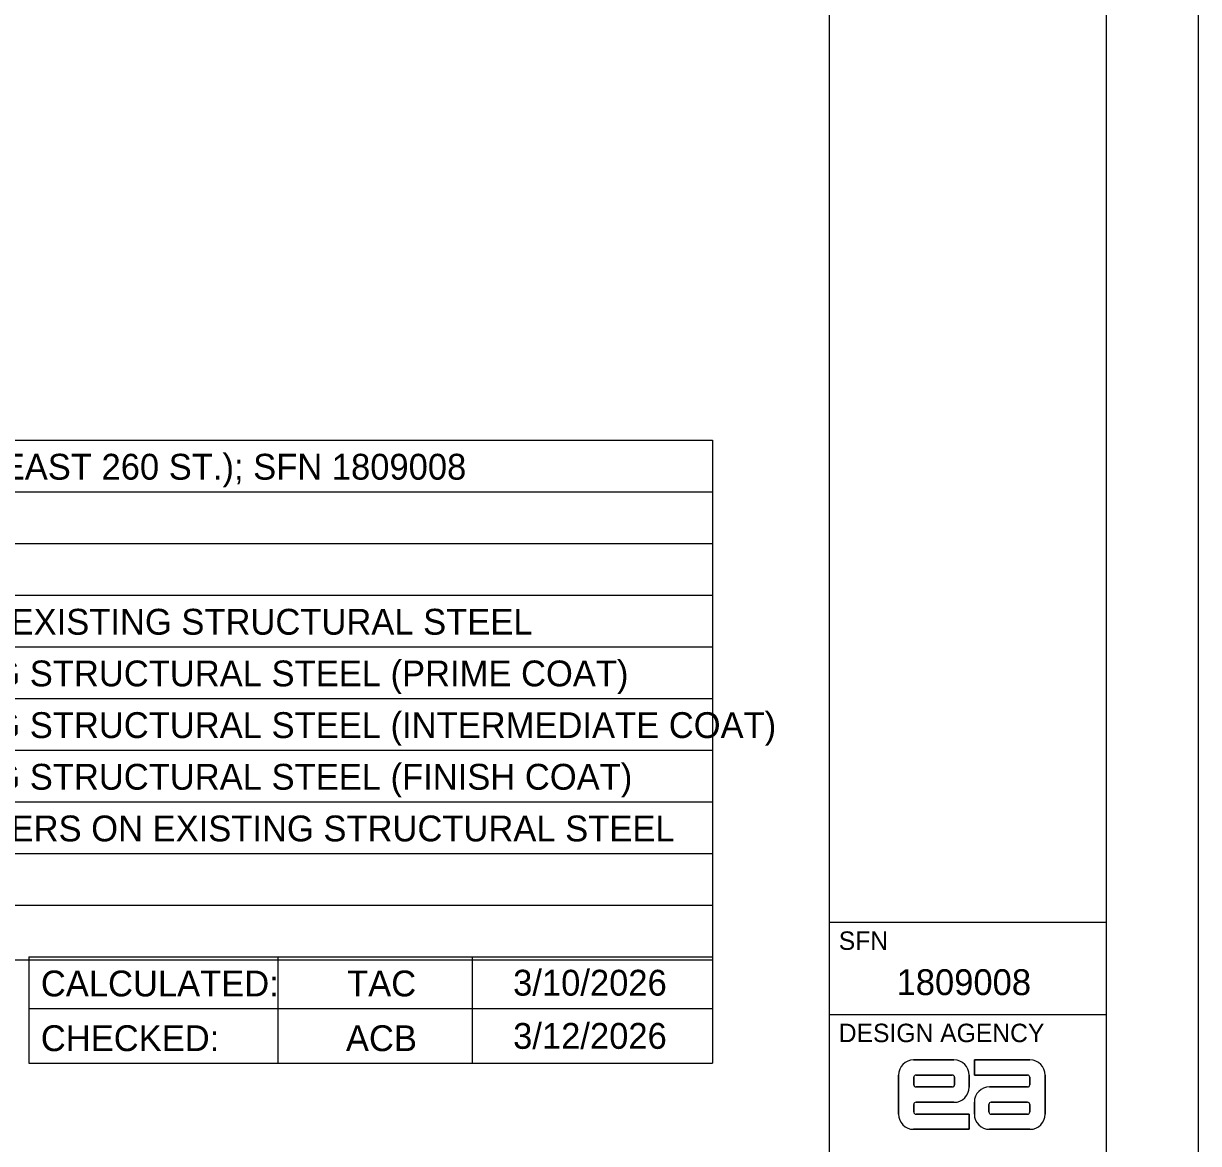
# Model space of a CAD drawing. Extents: x 0 to 34, y 0 to 22.
# Drawn here: x 27.63 to 34, y 4.3 to 10.37 of the extents above; entities that cross this region are included whole.
import ezdxf

# ---------------------------------------------------------------- set-up
doc = ezdxf.new("R2010")
doc.units = 0
for name, color, linetype in [('SH_Border', 7, 'Continuous'), ('SH_Cut_Line', 7, 'Continuous'), ('SH_Data', 7, 'Continuous'), ('SH_Text', 7, 'Continuous'), ('TX_X_20', 7, 'Continuous')]:
    doc.layers.add(name, color=color, linetype=linetype)

msp = doc.modelspace()

# ---------------------------------------------------------------- linework, layer by layer
at = {"layer": 'SH_Border'}
for p, q in [((32, 0.5), (32, 21.5)), ((32, 5.5), (33.5, 5.5)), ((32, 5), (33.5, 5))]:
    msp.add_line(p, q, dxfattribs=at)
msp.add_lwpolyline([(1.5, 21.5), (33.5, 21.5), (33.5, 0.5), (1.5, 0.5)], close=True, dxfattribs=at)
at = {"layer": 'SH_Cut_Line'}
msp.add_lwpolyline([(0, 0), (34, 0), (34, 22), (0, 22)], close=True, dxfattribs=at)
at = {"layer": 'SH_Text'}
for p, q in [((21.4824, 8.1121), (31.3648, 8.1121)), ((31.3648, 8.1121), (31.3648, 5.2956)), ((21.4824, 7.8321), (31.3648, 7.8321)), ((21.4824, 7.5521), (31.3648, 7.5521)), ((21.4824, 7.272), (31.3648, 7.272)), ((21.4824, 6.992), (31.3648, 6.992)), ((21.4824, 6.712), (31.3648, 6.712)), ((21.4824, 6.432), (31.3648, 6.432)), ((21.4824, 6.152), (31.3648, 6.152)), ((21.4824, 5.872), (31.3648, 5.872)), ((21.4824, 5.592), (31.3648, 5.592)), ((21.4824, 5.2956), (31.3648, 5.2956)), ((27.6589, 5.312), (31.3648, 5.312)), ((27.6589, 5.312), (27.6589, 4.7356)), ((29.0095, 5.312), (29.0095, 4.7356)), ((30.0636, 5.312), (30.0636, 4.7356)), ((31.3648, 5.312), (31.3648, 4.7356)), ((27.6589, 5.032), (31.3648, 5.032)), ((27.6589, 4.7356), (31.3648, 4.7356))]:
    msp.add_line(p, q, dxfattribs=at)
at = {"layer": 'TX_X_20'}
for p, q in [((32.6745, 4.7533), (32.456, 4.7533)), ((32.456, 4.7533), (32.6745, 4.7533)), ((32.785, 4.7533), (33.0865, 4.7533)), ((32.785, 4.6713), (32.785, 4.7533)), ((32.3739, 4.6713), (32.3739, 4.4597)), ((32.3739, 4.4597), (32.3739, 4.6713)), ((32.457, 4.6189), (32.457, 4.6594)), ((32.457, 4.6594), (32.457, 4.6189)), ((32.4688, 4.6713), (32.6656, 4.6713)), ((32.6656, 4.6713), (32.4688, 4.6713)), ((32.6775, 4.6594), (32.6775, 4.6189)), ((32.6775, 4.6189), (32.6775, 4.6594)), ((32.7566, 4.606), (32.7566, 4.6713)), ((32.7566, 4.6713), (32.7566, 4.606)), ((33.0737, 4.6713), (32.785, 4.6713)), ((33.0855, 4.6594), (33.0855, 4.6189)), ((33.0855, 4.6189), (33.0855, 4.6594)), ((33.1686, 4.4597), (33.1686, 4.6713)), ((33.1686, 4.6713), (33.1686, 4.4597)), ((32.6656, 4.607), (32.4688, 4.607)), ((32.4688, 4.607), (32.6656, 4.607)), ((33.0737, 4.607), (32.8671, 4.607)), ((32.8671, 4.607), (33.0737, 4.607)), ((32.4688, 4.524), (32.6745, 4.524)), ((32.6745, 4.524), (32.4688, 4.524)), ((32.785, 4.525), (32.785, 4.4597)), ((32.785, 4.4597), (32.785, 4.525)), ((32.876, 4.524), (33.0737, 4.524)), ((33.0737, 4.524), (32.876, 4.524)), ((32.457, 4.4716), (32.457, 4.5121)), ((32.457, 4.5121), (32.457, 4.4716)), ((32.4688, 4.4597), (32.7566, 4.4597)), ((32.7566, 4.4597), (32.7566, 4.3777)), ((32.8641, 4.4716), (32.8641, 4.5121)), ((32.8641, 4.5121), (32.8641, 4.4716)), ((33.0737, 4.4597), (32.876, 4.4597)), ((32.876, 4.4597), (33.0737, 4.4597)), ((33.0855, 4.5121), (33.0855, 4.4716)), ((33.0855, 4.4716), (33.0855, 4.5121)), ((32.7566, 4.3777), (32.456, 4.3777)), ((32.8671, 4.3777), (33.0865, 4.3777)), ((33.0865, 4.3777), (32.8671, 4.3777))]:
    msp.add_line(p, q, dxfattribs=at)
for points in [[(33.0865, 4.7533), (32.785, 4.7533), (32.785, 4.6713), (33.0737, 4.6713)], [(32.456, 4.3777), (32.7566, 4.3777), (32.7566, 4.4597), (32.4688, 4.4597)]]:
    msp.add_lwpolyline(points, dxfattribs=at)
for centre, radius, start, end in [((32.456, 4.6713), 0.0821, 90, 180), ((32.456, 4.6713), 0.0821, 90, 180), ((32.6745, 4.6713), 0.0821, 0, 90), ((32.6745, 4.6713), 0.0821, 0, 90), ((33.0865, 4.6713), 0.0821, 0, 90), ((33.0865, 4.6713), 0.0821, 0, 90), ((32.4688, 4.6594), 0.0119, 90, 180), ((32.4688, 4.6594), 0.0119, 90, 180), ((32.6656, 4.6594), 0.0119, 0, 90), ((32.6656, 4.6594), 0.0119, 0, 90), ((33.0737, 4.6594), 0.0119, 0, 90), ((33.0737, 4.6594), 0.0119, 0, 90), ((32.4688, 4.6189), 0.0119, 180, 270), ((32.4688, 4.6189), 0.0119, 180, 270), ((32.6656, 4.6189), 0.0119, 270, 0), ((32.6656, 4.6189), 0.0119, 270, 0), ((32.6745, 4.606), 0.0821, 270, 360), ((32.6745, 4.606), 0.0821, 270, 360), ((32.8671, 4.525), 0.0821, 90, 180), ((32.8671, 4.525), 0.0821, 90, 180), ((33.0737, 4.6189), 0.0119, 270, 0), ((33.0737, 4.6189), 0.0119, 270, 0), ((32.4688, 4.5121), 0.0119, 90, 180), ((32.4688, 4.5121), 0.0119, 90, 180), ((32.876, 4.5121), 0.0119, 90, 180), ((32.876, 4.5121), 0.0119, 90, 180), ((33.0737, 4.5121), 0.0119, 0, 90), ((33.0737, 4.5121), 0.0119, 0, 90), ((32.456, 4.4597), 0.0821, 180, 270), ((32.456, 4.4597), 0.0821, 180, 270), ((32.4688, 4.4716), 0.0119, 180, 270), ((32.4688, 4.4716), 0.0119, 180, 270), ((32.8671, 4.4597), 0.0821, 180, 270), ((32.8671, 4.4597), 0.0821, 180, 270), ((32.876, 4.4716), 0.0119, 180, 270), ((32.876, 4.4716), 0.0119, 180, 270), ((33.0737, 4.4716), 0.0119, 270, 0), ((33.0737, 4.4716), 0.0119, 270, 0), ((33.0865, 4.4597), 0.0821, 270, 360), ((33.0865, 4.4597), 0.0821, 270, 360)]:
    msp.add_arc(centre, radius, start, end, dxfattribs=at)

# ---------------------------------------------------------------- texts
at = {"layer": 'SH_Data'}
for s, height, p in [('SFN', 0.1, (32.05, 5.35)), ('1809008', 0.14, (32.3635, 5.105)), ('DESIGN AGENCY', 0.1, (32.05, 4.85))]:
    msp.add_text(s, height=height, dxfattribs=at).set_placement(p)
at = {"layer": 'SH_Text'}
for s, p in [('LOCATION 4; CUY-90-29.113; OVER S.R. 175 (EAST 260 ST.); SFN 1809008', (23.4654, 7.8979)), ('SURFACE PREPARATION OF EXISTING STRUCTURAL STEEL', (24.9083, 7.0579)), ('FIELD PAINTING OF EXISTING STRUCTURAL STEEL (PRIME COAT)', (24.9083, 6.7779)), ('FIELD PAINTING OF EXISTING STRUCTURAL STEEL (INTERMEDIATE COAT)', (24.9083, 6.4979)), ('FIELD PAINTING OF EXISTING STRUCTURAL STEEL (FINISH COAT)', (24.9083, 6.2179)), ('GRINDING FINS, TEARS, SLIVERS ON EXISTING STRUCTURAL STEEL', (24.9083, 5.9379)), ('CALCULATED:', (27.7248, 5.0979)), ('TAC', (29.3849, 5.0979)), ('3/10/2026', (30.2849, 5.102)), ('CHECKED:', (27.7248, 4.8014)), ('ACB', (29.3786, 4.8014)), ('3/12/2026', (30.2849, 4.8138))]:
    msp.add_text(s, height=0.14, dxfattribs=at).set_placement(p)

doc.saveas('drawing.dxf')
